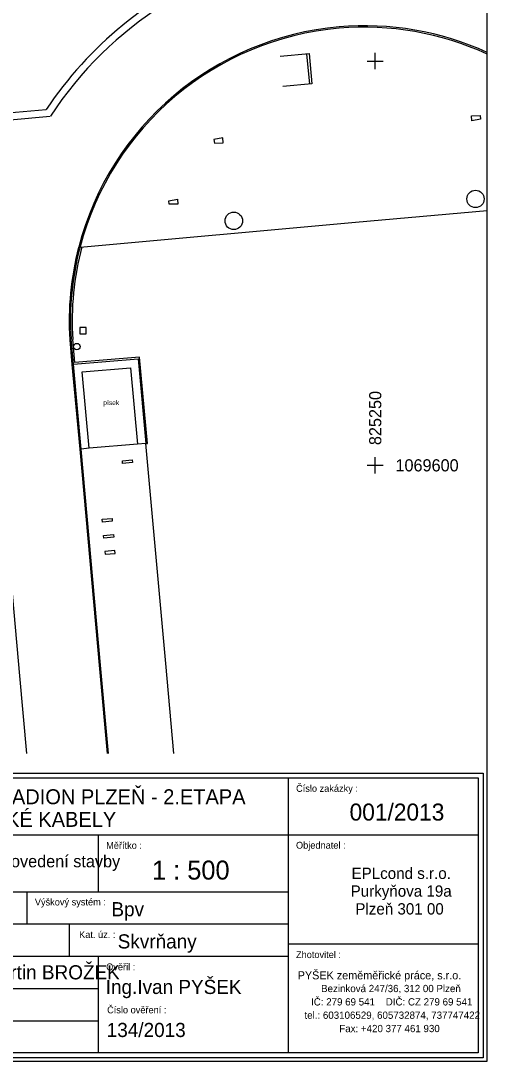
# Model space of a CAD drawing. Extents: x -825369 to -825236, y -1069674 to -1069474.
# Drawn here: x -825293.8 to -825236.2, y -1069673.7 to -1069545 of the extents above; entities that cross this region are included whole.
import ezdxf

# ---------------------------------------------------------------- set-up
doc = ezdxf.new("R2010")
doc.units = 0
for name, color, linetype in [('Vrstva 15', 7, 'Continuous'), ('Vrstva 16', 7, 'Continuous'), ('Vrstva 17', 7, 'Continuous'), ('Vrstva 18', 7, 'Continuous'), ('Vrstva 19', 7, 'Continuous'), ('Vrstva 20', 7, 'Continuous'), ('Vrstva 21', 7, 'Continuous'), ('Vrstva 22', 7, 'Continuous'), ('Vrstva 24', 7, 'Continuous'), ('Vrstva 25', 7, 'Continuous'), ('Vrstva 30', 7, 'Continuous'), ('Vrstva 63', 7, 'Continuous'), ('Vrstva 8', 7, 'Continuous')]:
    doc.layers.add(name, color=color, linetype=linetype)

msp = doc.modelspace()

# ---------------------------------------------------------------- linework, layer by layer
at = {"layer": 'Vrstva 15'}
for points in [[(-825293.05, -1069635.63), (-825293.92, -1069626.03), (-825296.4, -1069598.71), (-825298.57, -1069574.53), (-825300.1, -1069557.71), (-825290.15, -1069556.82)], [(-825286.47, -1069573), (-825252.42, -1069569.94), (-825236.17, -1069568.47)], [(-825278.39, -1069597.29), (-825275.93, -1069624.52), (-825274.93, -1069635.63)]]:
    msp.add_lwpolyline(points, dxfattribs=at)
msp.add_arc((-825251.14, -1069582.37), 46.63, 97.9601, 146.7725, dxfattribs=at)
at = {"layer": 'Vrstva 16'}
msp.add_line((-825285.34, -1069597.88), (-825286.35, -1069598), dxfattribs=at)
for points in [[(-825287.75, -1069584.46), (-825287.48, -1069587.55), (-825286.52, -1069598.01), (-825284.07, -1069625.17), (-825283.12, -1069635.63)], [(-825282.96, -1069635.63), (-825283.89, -1069625.18), (-825286.35, -1069598), (-825287.29, -1069587.51), (-825287.58, -1069584.41)], [(-825287.29, -1069587.51), (-825279.3, -1069586.83), (-825278.35, -1069597.29), (-825279.37, -1069597.37)]]:
    msp.add_lwpolyline(points, dxfattribs=at)
for centre, radius, start, end in [((-825251.34, -1069582.17), 36.53, 65.4579, 94.9024), ((-825251.31, -1069582.14), 36.49, 94.9441, 165.5334), ((-825251.28, -1069582.18), 36.37, 94.9876, 165.376), ((-825251.38, -1069582.25), 36.43, 65.3201, 94.8246), ((-825251.52, -1069582.17), 36.3, 165.4001, 183.6153), ((-825251.67, -1069582.14), 35.99, 165.2782, 183.6089)]:
    msp.add_arc(centre, radius, start, end, dxfattribs=at)
at = {"layer": 'Vrstva 17'}
msp.add_lwpolyline([(-825286.21, -1069588.44), (-825280.23, -1069587.94), (-825279.37, -1069597.37), (-825285.34, -1069597.88)], close=True, dxfattribs=at)
at = {"layer": 'Vrstva 19'}
msp.add_line((-825278.39, -1069597.33), (-825278.15, -1069597.31), dxfattribs=at)
msp.add_lwpolyline([(-825278.15, -1069597.31), (-825279.12, -1069586.61), (-825287.13, -1069587.29), (-825287.38, -1069584.44)], dxfattribs=at)
msp.add_arc((-825251.53, -1069582.16), 35.92, 165.1979, 183.643, dxfattribs=at)
at = {"layer": 'Vrstva 20'}
for centre, radius in [((-825237.61, -1069567.06), 1.07), ((-825267.48, -1069569.77), 1.08)]:
    msp.add_circle(centre, radius, dxfattribs=at)
at = {"layer": 'Vrstva 21'}
for points in [[(-825281.25, -1069599.43), (-825280.02, -1069599.32), (-825280, -1069599.65), (-825281.21, -1069599.77)], [(-825283.75, -1069606.67), (-825282.52, -1069606.57), (-825282.5, -1069606.91), (-825283.72, -1069607.03)], [(-825283.58, -1069608.66), (-825282.35, -1069608.57), (-825282.32, -1069608.9), (-825283.54, -1069609.02)], [(-825283.4, -1069610.66), (-825283.36, -1069611), (-825282.14, -1069610.9), (-825282.17, -1069610.55)]]:
    msp.add_lwpolyline(points, close=True, dxfattribs=at)
at = {"layer": 'Vrstva 22'}
for points in [[(-825238.11, -1069556.76), (-825237.03, -1069556.75), (-825236.99, -1069557.19), (-825238.07, -1069557.38)], [(-825269.93, -1069559.72), (-825269.88, -1069560.16), (-825268.79, -1069560.13), (-825268.85, -1069559.51)], [(-825275.51, -1069567.27), (-825274.44, -1069567.09), (-825274.39, -1069567.72), (-825275.47, -1069567.71)]]:
    msp.add_lwpolyline(points, close=True, dxfattribs=at)
at = {"layer": 'Vrstva 24'}
for p, q in [((-825285.72, -1069582.94), (-825286.52, -1069582.94)), ((-825286.52, -1069582.94), (-825286.52, -1069583.74)), ((-825285.72, -1069583.74), (-825285.72, -1069582.94)), ((-825286.52, -1069583.74), (-825285.72, -1069583.74))]:
    msp.add_line(p, q, dxfattribs=at)
at = {"layer": 'Vrstva 25'}
msp.add_line((-825258.49, -1069549.1), (-825258.13, -1069552.85), dxfattribs=at)
msp.add_lwpolyline([(-825261.76, -1069549.4), (-825258.16, -1069549.07), (-825257.84, -1069552.82), (-825261.43, -1069553.14)], dxfattribs=at)
at = {"layer": 'Vrstva 30'}
msp.add_lwpolyline([(-825300.1, -1069557.71), (-825300.16, -1069556.84), (-825290.67, -1069556.01)], dxfattribs=at)
msp.add_arc((-825251.17, -1069582.34), 47.47, 112.185, 146.314, dxfattribs=at)
at = {"layer": 'Vrstva 63'}
for p, q in [((-825236.17, -1069673.69), (-825236.17, -1069474.11)), ((-825260.73, -1069645.69), (-825260.73, -1069638.65)), ((-825325.26, -1069645.69), (-825237.27, -1069645.69)), ((-825284.2, -1069652.73), (-825284.2, -1069645.69)), ((-825260.73, -1069672.67), (-825260.73, -1069645.69)), ((-825325.26, -1069652.73), (-825260.73, -1069652.73)), ((-825293, -1069656.72), (-825293, -1069652.73)), ((-825325.26, -1069656.72), (-825260.73, -1069656.72)), ((-825287.76, -1069660.71), (-825287.76, -1069656.72)), ((-825260.73, -1069659.18), (-825237.27, -1069659.18)), ((-825325.26, -1069660.71), (-825260.73, -1069660.71)), ((-825284.2, -1069672.67), (-825284.2, -1069660.71)), ((-825325.26, -1069664.69), (-825284.2, -1069664.69)), ((-825325.26, -1069668.68), (-825284.2, -1069668.68)), ((-825368.52, -1069673.69), (-825236.17, -1069673.69))]:
    msp.add_line(p, q, dxfattribs=at)
for points in [[(-825250, -1069551), (-825250, -1069550), (-825250, -1069549)], [(-825251, -1069550), (-825250, -1069550), (-825249, -1069550)], [(-825250, -1069601), (-825250, -1069600), (-825250, -1069599)], [(-825251, -1069600), (-825250, -1069600), (-825249, -1069600)]]:
    msp.add_lwpolyline(points, dxfattribs=at)
for points in [[(-825325.86, -1069638.05), (-825236.67, -1069638.05), (-825236.67, -1069673.27), (-825325.86, -1069673.27)], [(-825325.26, -1069638.65), (-825237.27, -1069638.65), (-825237.27, -1069672.67), (-825325.26, -1069672.67)]]:
    msp.add_lwpolyline(points, close=True, dxfattribs=at)
at = {"layer": 'Vrstva 8'}
msp.add_circle((-825286.87, -1069585.32), 0.4, dxfattribs=at)

# ---------------------------------------------------------------- texts
at = {"layer": 'Vrstva 18'}
msp.add_text('písek', height=0.6, dxfattribs=at).set_placement((-825283.61, -1069592.55))
at = {"layer": 'Vrstva 63'}
for s, height, rotation, p in [('825250', 1.5, 90, (-825249.25, -1069597.5)), ('LEHKOATLETICKÝ STADION PLZEŇ - 2.ETAPA', 1.85, 360, (-825320.6, -1069641.91)), ('Číslo zakázky :', 0.85, 0.0291, (-825259.78, -1069640.38)), ('001/2013', 2.1, 360, (-825253.17, -1069643.93)), ('Měřítko :', 0.85, 0.0291, (-825283.25, -1069647.43)), ('Objednatel :', 0.85, 0.0291, (-825259.79, -1069647.41)), ('1 : 500', 2.346, 360, (-825277.59, -1069651.23)), ('Výškový systém :', 0.85, 0.0291, (-825292.06, -1069654.43)), ('Bpv', 1.75, 360, (-825282.6, -1069655.77)), ('Kat. úz. :', 0.85, 0.0291, (-825286.59, -1069658.46)), ('Skvrňany', 1.75, 360, (-825281.82, -1069659.75)), ('Zhotovitel :', 0.85, 0.0291, (-825259.79, -1069660.94)), ('Ing.Ivan PYŠEK,Martin BROŽEK', 1.75, 360, (-825315.77, -1069663.57)), ('Ověřil :', 0.85, 0.0291, (-825283.25, -1069662.45)), ('Ing.Ivan PYŠEK', 1.75, 360, (-825283.3, -1069665.38)), ('Číslo ověření :', 0.85, 0.0291, (-825283.13, -1069667.77))]:
    msp.add_text(s, height=height, rotation=rotation, dxfattribs=at).set_placement(p)
for s, height, p in [('1069600', 1.5, (-825247.5, -1069600.75)), ('OPTICKÉ KABELY', 1.85, (-825303.18, -1069644.71)), ('Zaměření skutečného provedení stavby ', 1.5, (-825316.75, -1069649.71)), ('EPLcond s.r.o.', 1.4, (-825252.93, -1069651.15)), ('Purkyňova 19a', 1.4, (-825253.04, -1069653.35)), ('Plzeň 301 00', 1.4, (-825252.46, -1069655.55)), ('PYŠEK zeměměřické práce, s.r.o.', 1, (-825259.58, -1069663.57)), ('Bezinková 247/36, 312 00 Plzeň', 0.9, (-825256.69, -1069665.15)), ('IČ: 279 69 541    DIČ: CZ 279 69 541', 0.9, (-825257.93, -1069666.8)), ('tel.: 603106529, 605732874, 737747422', 0.9, (-825258.74, -1069668.45)), ('134/2013', 1.75, (-825283.18, -1069670.7)), ('Fax: +420 377 461 930', 0.9, (-825254.44, -1069670.1))]:
    msp.add_text(s, height=height, dxfattribs=at).set_placement(p)

doc.saveas('drawing.dxf')
